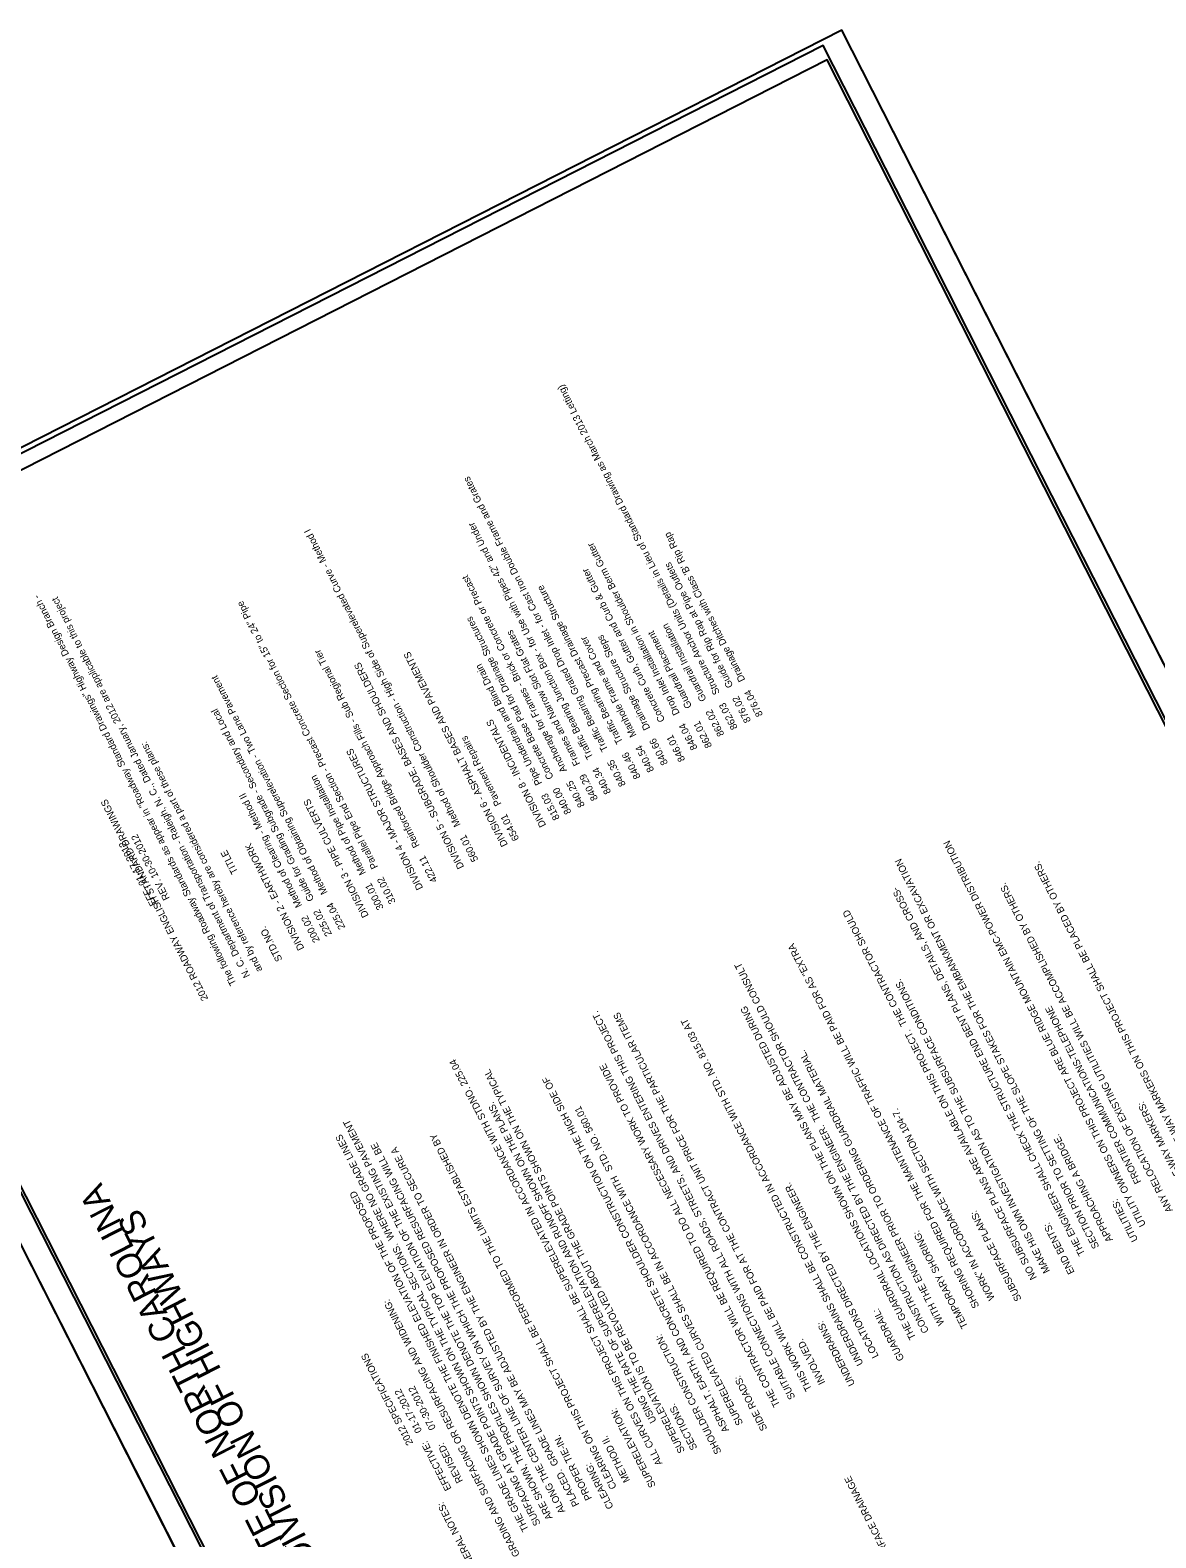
# Model space of a CAD drawing. Extents: x 558484 to 564063, y 513718 to 518374.
# Drawn here: x 562607 to 563568, y 517087 to 518374 of the extents above; entities that cross this region are included whole.
import ezdxf

# ---------------------------------------------------------------- set-up
doc = ezdxf.new("R2010")
doc.units = 0
for name, color, linetype in [('Default', 7, 'Continuous'), ('Sheet Cutting Line CELL', 7, 'Continuous'), ('Sheet Data Text CELL', 7, 'Continuous'), ('Sheet Plan CELL', 7, 'Continuous'), ('Sheet Plot Border Inside CELL', 7, 'Continuous'), ('Sheet Plot Border Outside CELL', 7, 'Continuous'), ('Sheet Symbology CELL', 7, 'Continuous')]:
    doc.layers.add(name, color=color, linetype=linetype)

msp = doc.modelspace()

# ---------------------------------------------------------------- linework, layer by layer
at = {"layer": 'Sheet Cutting Line CELL'}
for p, q in [((564062.7, 516873.6), (563299.7, 518374.3)), ((562323.6, 517878), (563086.6, 516377.3))]:
    msp.add_line(p, q, dxfattribs=at)
at = {"layer": 'Sheet Plan CELL'}
msp.add_lwpolyline([(562351.4, 517873), (563031.2, 516535.9), (563967.2, 517011.8), (563287.3, 518348.9)], close=True, dxfattribs=at)
at = {"layer": 'Sheet Plot Border Inside CELL'}
msp.add_lwpolyline([(564039, 516876.1), (563283.9, 518361.2), (562343.5, 517883), (563098.5, 516398)], close=True, dxfattribs=at)
at = {"layer": 'Sheet Plot Border Outside CELL'}
msp.add_lwpolyline([(564062.7, 516873.6), (563299.7, 518374.3), (562323.6, 517878), (563086.6, 516377.3)], close=True, dxfattribs=at)

# ---------------------------------------------------------------- texts
at = {"layer": 'Default'}
for s, rotation, p in [('862.03    Structure Anchor Units (Details in Lieu of Standard Drawing as March 2013 Letting)', 116.9605, (563211, 517778.9)), ('840.35    Traffic Bearing Grated Drop Inlet - for Cast Iron Double Frame and Grates', 116.9605, (563115.5, 517730.3)), ('560.01    Method of Shoulder Construction - High Side of Superelevated Curve - Method I', 116.9605, (562989.5, 517666.1)), ('840.34    Traffic Bearing Junction Box - for Use with Pipes 42" and Under', 116.9605, (563102.9, 517723.8)), ("876.04    Drainage Ditches with Class 'B' Rip Rap", 116.9605, (563232.6, 517789.9)), ('846.04    Drop Inlet Installation in Shoulder Berm Gutter', 116.9605, (563176.7, 517761.4)), ('876.02    Guide for Rip Rap at Pipe Outlets', 116.9605, (563222.4, 517784.7)), ('840.25    Anchorage for Frames - Brick or Concrete or Precast', 116.9605, (563080.5, 517712.5)), (' 846.01      Concrete Curb, Gutter and Curb & Gutter', 116.9605, (563167.2, 517749.5)), ('The following Roadway Standards as appear in "Roadway Standard Drawings" Highway Design Branch -', 116.9605, (562782.9, 517560.6)), ('N. C. Department of Transportation - Raleigh, N. C., Dated January, 2012 are applicable to this project', 116.9605, (562794.6, 517567.1)), ('840.46    Traffic Bearing Precast Drainage Structure', 116.9605, (563128.1, 517736.7)), ('310.02    Parallel Pipe End Section - Precast Concrete Section for 15" to 24" Pipe', 116.9605, (562919, 517630.2)), ('840.00    Concrete Base Pad for Drainage Structures', 116.9605, (563069, 517706.6)), ('862.02    Guardrail Installation', 116.9605, (563199.6, 517773.1)), ('840.29    Frames and Narrow Slot Flat Grates', 116.9605, (563091.7, 517718.2)), ('840.54    Manhole Frame and Cover', 116.9605, (563139.7, 517742.6)), ('840.66    Drainage Structure Steps', 116.9605, (563151.5, 517748.6)), (' 862.01      Guardrail Placement', 116.9605, (563190.2, 517761.2)), ('422.11    Reinforced Bridge Approach Fills - Sub Regional Tier', 116.9605, (562954.6, 517648.3)), ('DIVISION 6 - ASPHALT BASES AND PAVEMENTS', 116.9605, (563014.7, 517679)), ('DIVISION 5 - SUBGRADE, BASES AND SHOULDERS', 116.9605, (562977.4, 517660)), ('815.03    Pipe Underdrain and Blind Drain', 116.9605, (563059.1, 517701.6)), ('225.04    Method of Obtaining Superelevation - Two Lane Pavement', 116.9605, (562875.9, 517608.3)), ('225.02    Guide for Grading Subgrade - Secondary and Local', 116.9605, (562864.5, 517602.5)), ('DIVISION 8 - INCIDENTALS', 116.9605, (563047.4, 517695.6)), ('and by reference hereby are considered a part of these plans:', 116.9605, (562805.2, 517572)), ('654.01    Pavement Repairs', 116.9605, (563024.4, 517683.9)), ('DIVISION 4 - MAJOR STRUCTURES', 116.9605, (562942.4, 517642.1)), ('300.01    Method of Pipe Installation ', 116.9605, (562908.7, 517625)), ('2012 ROADWAY ENGLISH STANDARD DRAWINGS', 116.9605, (562758.8, 517547.5)), ('200.02    Method of Clearing - Method II', 116.9605, (562854.2, 517597.2)), ('DIVISION 3 - PIPE CULVERTS', 116.9605, (562895.9, 517618.5)), ('                                                      REV. 10-30-2012', 116.9605, (562780.5, 517526)), ('                                                      EFF. 01-17-2012', 116.9605, (562769.3, 517521.1)), ('STD.NO.                       TITLE', 116.9605, (562822.2, 517580.9)), ('DIVISION 2 - EARTHWORK', 116.9605, (562840.9, 517590.5)), ('         UTILITY OWNERS ON THIS PROJECT ARE BLUE RIDGE MOUNTAIN EMC-POWER DISTRIBUTION', 117.0942, (563568.8, 517336.7)), ('         SECTION PRIOR TO SETTING OF THE SLOPE STAKES FOR THE EMBANKMENT OR EXCAVATION ', 117.0942, (563529, 517318)), ('         ALL RIGHT-OF-WAY MARKERS ON THIS PROJECT SHALL BE PLACED BY OTHERS.  ', 117.0942, (563622.3, 517364.2)), ('         ANY RELOCATION OF EXISTING UTILITIES WILL BE ACCOMPLISHED BY OTHERS.  ', 117.0942, (563591.8, 517349)), ('         THE ENGINEER SHALL CHECK THE STRUCTURE END BENT PLANS, DETAILS, AND CROSS-', 117.0942, (563516.9, 517312)), ('         NO SUBSURFACE PLANS ARE AVAILABLE ON THIS PROJECT.  THE CONTRACTOR SHOULD ', 117.0942, (563475.6, 517291.5)), ('         SHORING REQUIRED FOR THE MAINTENANCE OF TRAFFIC WILL BE PAID FOR AS "EXTRA ', 117.0942, (563426.5, 517267.2)), ('         CONSTRUCTION AS DIRECTED BY THE ENGINEER.  THE CONTRACTOR SHOULD CONSULT', 117.0942, (563383.5, 517245.9)), ('         MAKE HIS OWN INVESTIGATION AS TO THE SUBSURFACE CONDITIONS.  ', 117.0942, (563486.8, 517297.1)), ('         SUITABLE CONNECTIONS WITH ALL ROADS, STREETS, AND DRIVES ENTERING THIS PROJECT.  ', 117.0942, (563269.4, 517189.3)), ('         THIS WORK WILL BE PAID FOR AT THE CONTRACT UNIT PRICE FOR THE PARTICULAR ITEMS ', 117.0942, (563283.6, 517196.4)), ('         THE GUARDRAIL LOCATIONS SHOWN ON THE PLANS MAY BE ADJUSTED DURING ', 117.0942, (563372.4, 517240.3)), ('FRONTIER COMMUNICATIONS-TELEPHONE', 117.0942, (563555.7, 517391.2)), ('         UNDERDRAINS SHALL BE CONSTRUCTED IN ACCORDANCE WITH STD. NO. 815.03 AT ', 117.0942, (563327.5, 517218.1)), ('         NO. 225.04', 117.0942, (562997.4, 517442.1)), ('         THE CONTRACTOR WILL BE REQUIRED TO DO ALL NECESSARY WORK TO PROVIDE ', 117.0942, (563256.3, 517182.8)), ('         WITH THE ENGINEER PRIOR TO ORDERING GUARDRAIL MATERIAL.', 117.0942, (563396.7, 517252.4)), ('        SUPERELEVATION IS TO BE REVOLVED ABOUT THE GRADE POINTS SHOWN ON THE TYPICAL ', 117.0942, (563174.1, 517145.5)), ('         ASPHALT, EARTH, AND CONCRETE SHOULDER CONSTRUCTION ON THE HIGH SIDE OF', 117.0942, (563212.8, 517161.3)), ('         ALL CURVES ON THIS PROJECT SHALL BE SUPERELEVATED IN ACCORDANCE WITH STD. ', 117.0942, (563155.9, 517133)), ('USING THE RATE OF SUPERELEVATION AND RUNOFF SHOWN ON THE PLANS. ', 117.0942, (563141.7, 517187)), ('       STD. NO. 560.01', 117.0942, (563111.6, 517387.8)), ('         WORK" IN ACCORDANCE WITH SECTION 104-7.  ', 117.0942, (563439.8, 517273.8)), ('RIGHT-OF-WAY MARKERS:  ', 117.0942, (563604.5, 517367.9)), ('         ARE SHOWN, THE PROFILES SHOWN DENOTE THE TOP ELEVATION OF THE EXISTING PAVEMENT ', 117.0942, (563062.2, 517086.6)), ('         SURFACING AT GRADE POINTS SHOWN ON THE TYPICAL SECTIONS.  WHERE NO GRADE LINES ', 117.0942, (563051.8, 517081.5)), ('         CLEARING ON THIS PROJECT SHALL BE PERFORMED TO THE LIMITS ESTABLISHED BY ', 117.0942, (563116.8, 517112.7)), ('         APPROACHING A BRIDGE.  ', 117.0942, (563540.6, 517323.7)), ('         ALONG THE CENTER LINE OF SURVEY ON WHICH THE PROPOSED RESURFACING WILL BE ', 117.0942, (563073, 517092)), ('         PLACED.  GRADE LINES MAY BE ADJUSTED BY THE ENGINEER IN ORDER TO SECURE A ', 117.0942, (563084.9, 517097.9)), ('         SUPERELEVATED CURVES SHALL BE IN ACCORDANCE WITH ', 117.0942, (563224.8, 517167.2)), ('         LOCATIONS DIRECTED BY THE ENGINEER.  ', 117.0942, (563340.6, 517224.6)), ('         THE GRADE LINES SHOWN DENOTE THE FINISHED ELEVATION OF THE PROPOSED ', 117.0942, (563041.7, 517076.5)), ('UTILITIES:  ', 117.0942, (563553, 517341.7)), ('SUBSURFACE PLANS:  ', 117.0942, (563453.5, 517291)), ('END BENTS:  ', 117.0942, (563498.8, 517314.1)), ('TEMPORARY SHORING:  ', 117.0942, (563407.7, 517267.7)), ('GRADING AND SURFACING OR RESURFACING AND WIDENING:  ', 117.0942, (563025, 517072.8)), ('GUARDRAIL:  ', 117.0942, (563353.3, 517240)), ('SHOULDER CONSTRUCTION:  ', 117.0942, (563197.2, 517160.5)), ('UNDERDRAINS:  ', 117.0942, (563311.3, 517218.6)), ('         INVOLVED.  ', 117.0942, (563295, 517202)), ('GENERAL NOTES:                         2012 SPECIFICATIONS', 117.0942, (562991.3, 517055.7)), ('SIDE ROADS:  ', 117.0942, (563236.3, 517180.4)), ('                                       EFFECTIVE:    01-17-2012', 117.0942, (563006.2, 517051.9)), ('                                       REVISED:      07-30-2012', 117.0942, (563016, 517058.4)), ('SUPERELEVATION:  ', 117.0942, (563141.1, 517131.9)), ('         SECTIONS.  ', 117.0942, (563185.7, 517146.1)), ('         PROPER TIE-IN.  ', 117.0942, (563095.7, 517103.2)), ('         METHOD II.', 117.0942, (563128.2, 517118.4)), ('CLEARING:  ', 117.0942, (563105, 517113.6))]:
    msp.add_text(s, height=6, rotation=rotation, dxfattribs=at).set_placement(p)
at = {"layer": 'Sheet Data Text CELL'}
msp.add_text('SHOULDER BERM SUMMARY, AND SUBSURFACE DRAINAGE', height=6, rotation=116.9503, dxfattribs=at).set_placement((563413.9, 516930.5))
at = {"layer": 'Sheet Symbology CELL'}
for s, p in [('STATE OF NORTH CAROLINA', (562850.2, 517030.9)), ('DIVISION OF HIGHWAYS', (562852.4, 517068.9))]:
    msp.add_text(s, height=21.419, rotation=116.9503, dxfattribs=at).set_placement(p)

doc.saveas('drawing.dxf')
